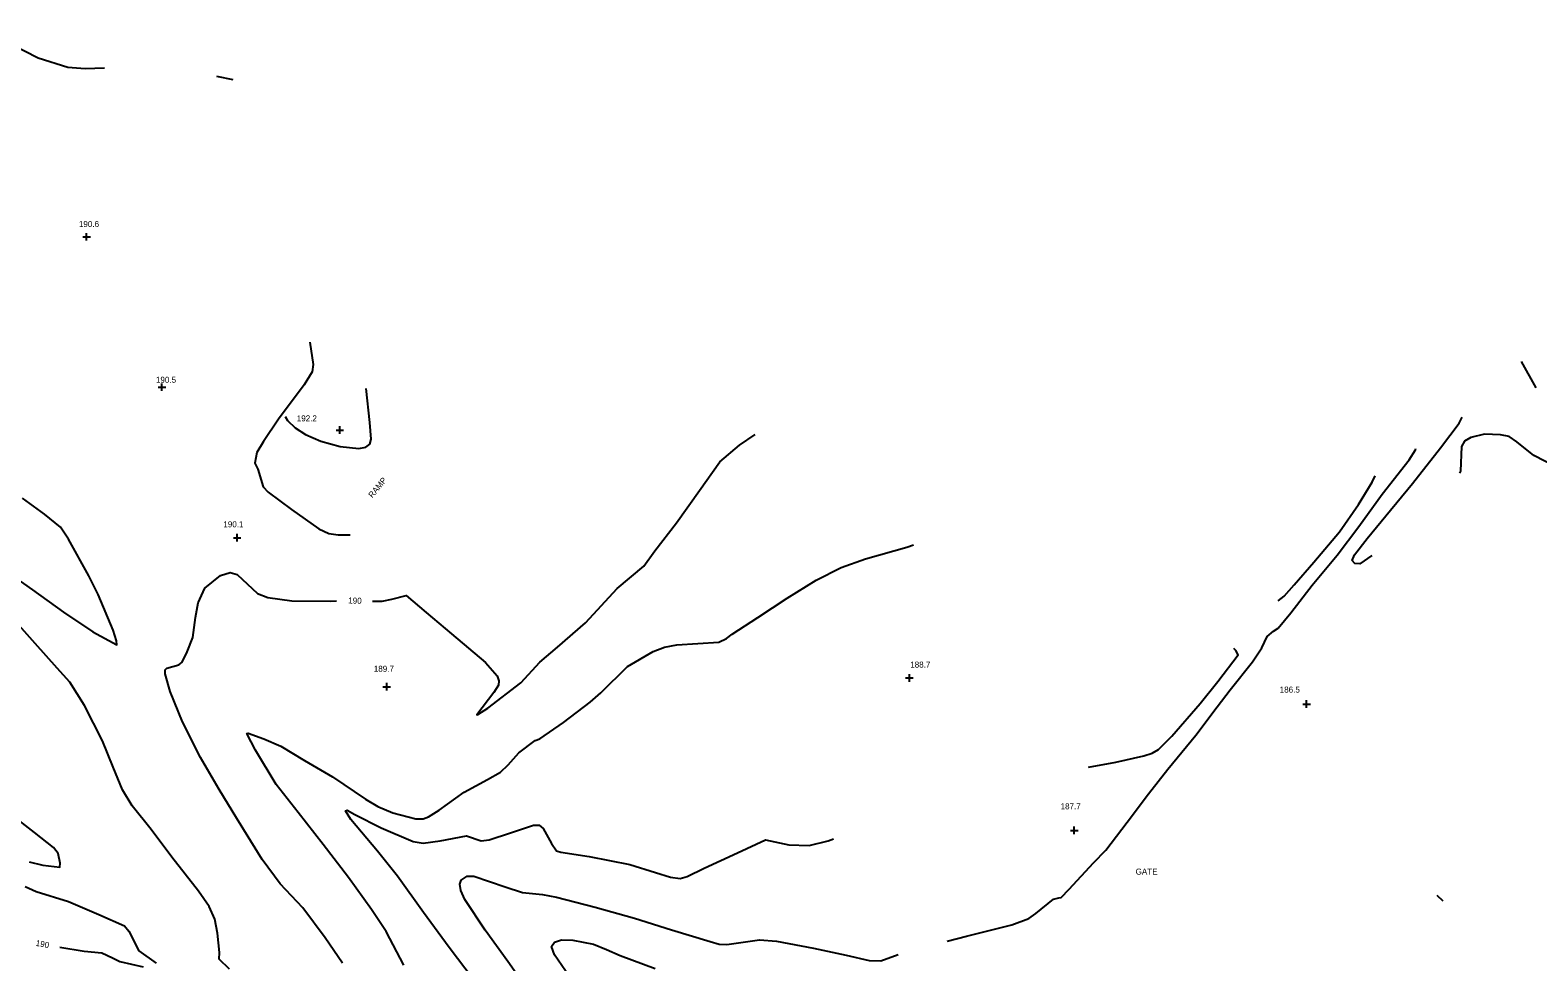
# Model space of a CAD drawing. Extents: x 1467615 to 2003689, y 770235 to 1108726.
# Drawn here: x 1995231 to 1995732, y 776984 to 777294 of the extents above; entities that cross this region are included whole.
import ezdxf

# ---------------------------------------------------------------- set-up
doc = ezdxf.new("R2010")
doc.units = 0
for name, color, linetype in [('RD_DTM_Major1', 7, 'Continuous'), ('RD_DTM_Major1_Lbl', 7, 'Continuous'), ('RD_DTM_Minor1', 7, 'Continuous'), ('RD_DTM_Spot_Elev', 7, 'Continuous'), ('RD_TX_Misc1', 7, 'Continuous')]:
    doc.layers.add(name, color=color, linetype=linetype)

msp = doc.modelspace()

# ---------------------------------------------------------------- linework, layer by layer
at = {"layer": 'RD_DTM_Major1'}
msp.add_line((1995731.45, 777174.81), (1995726.55, 777183.55), dxfattribs=at)
for points in [[(1995344.99, 777103.94), (1995348.16, 777103.86), (1995351.39, 777104.58), (1995356.09, 777105.75), (1995362.72, 777100.15), (1995371.16, 777093.09), (1995382.44, 777083.49), (1995386.33, 777079.12), (1995386.91, 777077.44), (1995386.75, 777076.02), (1995385.21, 777073.61), (1995379.55, 777066.14), (1995379.94, 777066.2), (1995383.22, 777068.33), (1995394.25, 777076.83), (1995400.51, 777083.66), (1995406.37, 777088.65), (1995415.73, 777096.7), (1995426.18, 777108.16), (1995435.08, 777115.59), (1995438.73, 777120.59), (1995445.91, 777129.91), (1995453.54, 777140.7), (1995460.3, 777150.18), (1995466.87, 777155.72), (1995472.09, 777159.26)], [(1995334.99, 776983.68), (1995329.2, 776992.08), (1995321.78, 777001.98), (1995314.32, 777010.01), (1995308.26, 777018.05), (1995299.89, 777031.68), (1995294.04, 777041.29), (1995287.86, 777051.96), (1995281.86, 777063.8), (1995277.71, 777073.89), (1995276.04, 777079.82), (1995276.11, 777081.1), (1995276.62, 777081.67), (1995280.62, 777082.71), (1995281.68, 777083.69), (1995283.43, 777087.1), (1995285.29, 777091.83), (1995286.17, 777098.47), (1995287.06, 777103.33), (1995289.27, 777108.19), (1995294.5, 777112.42), (1995297.64, 777113.39), (1995300.05, 777112.73), (1995306.74, 777106.48), (1995310.21, 777105.08), (1995318.14, 777103.99), (1995330.94, 777103.86), (1995332.99, 777104.03)], [(1995241.11, 776988.93), (1995249.15, 776987.6), (1995255.05, 776987.02), (1995258.63, 776985.43), (1995261.03, 776984.21), (1995268.76, 776982.39)]]:
    msp.add_lwpolyline(points, dxfattribs=at)
at = {"layer": 'RD_DTM_Minor1'}
for p, q in [((1995293.18, 777278.35), (1995298.61, 777277.3)), ((1995698.46, 777006.18), (1995700.45, 777004.39))]:
    msp.add_line(p, q, dxfattribs=at)
for points in [[(1995215.8, 777293.66), (1995233.93, 777284.46), (1995243.72, 777281.39), (1995249.47, 777280.95), (1995255.96, 777281.1)], [(1995324.13, 777189.93), (1995325.27, 777182.59), (1995324.93, 777180.17), (1995322.29, 777175.77), (1995313.68, 777164.34), (1995308.73, 777156.97), (1995306.51, 777153.34), (1995305.82, 777149.73), (1995306.84, 777147.75), (1995308.67, 777141.87), (1995310.32, 777140.08), (1995318, 777134.4), (1995327.09, 777128), (1995330.43, 777126.45), (1995333.56, 777125.96), (1995337.49, 777125.99)], [(1995315.99, 777165.26), (1995316.77, 777163.94), (1995319.3, 777161.53), (1995322.68, 777159.35), (1995327.74, 777157.07), (1995334.17, 777155.28), (1995340.46, 777154.69), (1995342.71, 777155.1), (1995344.02, 777156.12), (1995344.53, 777157.8), (1995344.11, 777163.25), (1995342.8, 777174.57)], [(1995676.83, 777119.08), (1995672.87, 777116.36), (1995671.24, 777116.47), (1995670.32, 777117.47), (1995671.09, 777119.34), (1995675.35, 777124.78), (1995681.53, 777132.3), (1995690.37, 777143.02), (1995699.65, 777154.88), (1995705.83, 777163.06), (1995706.93, 777165.03)], [(1995741.16, 777146.94), (1995730.73, 777152.37), (1995724.99, 777156.83), (1995722.49, 777158.61), (1995719.63, 777159.21), (1995714.28, 777159.45), (1995709.79, 777158.26), (1995707.61, 777157.03), (1995706.61, 777155.29), (1995706.35, 777147.14), (1995706, 777146.47)], [(1995535.79, 776990.96), (1995542.29, 776992.57), (1995557.26, 776996.33), (1995562.97, 776998.45), (1995565.29, 777000.16), (1995571.15, 777004.87), (1995572.86, 777005.37), (1995573.71, 777005.42), (1995576.37, 777008.24), (1995584.39, 777016.94), (1995588.53, 777021.15), (1995595.64, 777030.48), (1995602.71, 777039.88), (1995609.17, 777048.04), (1995618.38, 777059.44), (1995625.49, 777068.76), (1995629.83, 777074.48), (1995637.27, 777083.79), (1995640.32, 777088.44), (1995642.13, 777092.13), (1995644.26, 777093.95), (1995645.81, 777094.95), (1995650.01, 777100.05), (1995657.09, 777109.25), (1995665.39, 777119.21), (1995672.55, 777128.7), (1995680.31, 777139.44), (1995689.32, 777150.89), (1995691.42, 777154.23), (1995691.51, 777154.67)], [(1995645.81, 777104.07), (1995647.79, 777105.55), (1995651.09, 777109.29), (1995657.6, 777116.87), (1995666.1, 777126.93), (1995672.4, 777136.04), (1995677.01, 777143.5), (1995678.01, 777145.6)], [(1995221.01, 777115.3), (1995232.03, 777107.73), (1995242.35, 777100.28), (1995252.03, 777093.76), (1995260, 777089.45), (1995259.87, 777090.73), (1995258.82, 777094.26), (1995253.81, 777106.08), (1995250.76, 777112.38), (1995244.01, 777124.54), (1995241.33, 777128.45), (1995236.01, 777132.83), (1995228.69, 777138.13)], [(1995355.34, 776982.93), (1995349.47, 776994.18), (1995344.6, 777001.51), (1995336.98, 777012.07), (1995328.55, 777023.03), (1995320.31, 777033.68), (1995313, 777042.95), (1995306.06, 777054.38), (1995303.21, 777059.91), (1995303.61, 777060.05), (1995308.91, 777058.21), (1995314.46, 777055.75), (1995322.41, 777051.02), (1995331.68, 777045.59), (1995342.64, 777038.16), (1995346.69, 777035.74), (1995351.75, 777033.6), (1995359.3, 777031.59), (1995361.74, 777031.54), (1995363.56, 777032.2), (1995367.06, 777034.47), (1995375.43, 777040.43), (1995383.19, 777044.67), (1995387.44, 777047.04), (1995390.02, 777049.49), (1995393.57, 777053.49), (1995399, 777057.6), (1995400.5, 777058.19), (1995408.38, 777063.56), (1995417.25, 777070.31), (1995420.76, 777073.47), (1995429.6, 777082.2), (1995438.14, 777087.24), (1995441.91, 777088.63), (1995446.08, 777089.39), (1995460.03, 777090.3), (1995462.53, 777091.49), (1995464.43, 777092.92), (1995472.9, 777098.48), (1995482.68, 777104.92), (1995492.36, 777110.87), (1995500.67, 777115.1), (1995508.72, 777118.02), (1995522.46, 777121.89), (1995524.59, 777122.6)], [(1995297.44, 776981.58), (1995294.01, 776985.01), (1995294.12, 776987.19), (1995293.51, 776993.64), (1995292.58, 776998.2), (1995290.75, 777002.42), (1995287.17, 777007.54), (1995278.29, 777018.82), (1995271.42, 777027.99), (1995265.08, 777035.9), (1995261.96, 777041.22), (1995258.84, 777048.79), (1995255.3, 777057.51), (1995249.29, 777069.28), (1995244.47, 777077.01), (1995240.23, 777081.65), (1995232.86, 777089.87), (1995223.94, 777099.96)], [(1995582.81, 777048.76), (1995591.83, 777050.47), (1995601.15, 777052.48), (1995603.88, 777053.43), (1995605.99, 777054.68), (1995610.48, 777059.02), (1995619.83, 777069.91), (1995625.69, 777077.19), (1995632.47, 777086.09), (1995631.71, 777087.55), (1995631.05, 777088.17)], [(1995230.87, 777017.33), (1995235.48, 777016.2), (1995241.15, 777015.56), (1995241.26, 777016.88), (1995240.56, 777020.07), (1995238.99, 777022.01), (1995232.65, 777027.04), (1995221.73, 777035.6)], [(1995378.35, 776978.36), (1995370.36, 776988.85), (1995361.88, 777000.41), (1995353.25, 777012.54), (1995346.65, 777020.85), (1995337.79, 777031.36), (1995335.95, 777034.24), (1995336.48, 777034.42), (1995339.11, 777033.01), (1995347.83, 777028.63), (1995358.42, 777024.02), (1995361.82, 777023.5), (1995367.45, 777024.23), (1995376.21, 777025.98), (1995380.99, 777024.28), (1995383.67, 777024.59), (1995390.82, 777026.97), (1995398.39, 777029.5), (1995400.34, 777029.44), (1995401.59, 777028.42), (1995404.39, 777023.44), (1995406.03, 777020.91), (1995407.47, 777020.53), (1995416.95, 777019.03), (1995430.47, 777016.36), (1995438.94, 777013.78), (1995443.91, 777012.18), (1995447.09, 777011.8), (1995449.48, 777012.46), (1995455.15, 777015.2), (1995466.19, 777020.3), (1995475.48, 777024.57), (1995483.19, 777022.96), (1995489.96, 777022.72), (1995496.26, 777024.28), (1995498.07, 777024.95)], [(1995229.54, 777009.12), (1995233.24, 777007.48), (1995244.03, 777004.17), (1995254, 776999.75), (1995262.59, 776996.04), (1995264.04, 776994.3), (1995267.35, 776987.72), (1995273.04, 776983.67)], [(1995397.21, 776973.78), (1995389.94, 776984.22), (1995382.38, 776994.56), (1995375.63, 777004.83), (1995374.32, 777007.74), (1995373.99, 777009.86), (1995374.43, 777011.25), (1995376.34, 777012.5), (1995378.57, 777012.5), (1995388.98, 777008.95), (1995394.82, 777007.11), (1995401.36, 777006.46), (1995406.03, 777005.58), (1995418.94, 777002.22), (1995431.95, 776998.56), (1995444.21, 776994.75), (1995457.06, 776990.83), (1995460.13, 776989.93), (1995462.66, 776989.87), (1995473.51, 776991.42), (1995479.13, 776990.92), (1995491.38, 776988.56), (1995502.28, 776986.31), (1995509.87, 776984.54), (1995513.83, 776984.41), (1995519.57, 776986.54)], [(1995413.91, 776974), (1995405.43, 776986.35), (1995404.45, 776989.11), (1995405.35, 776990.59), (1995407.75, 776991.37), (1995411.45, 776991.3), (1995418.4, 776989.92), (1995422.63, 776988.17), (1995427.16, 776986.17), (1995438.79, 776981.81)]]:
    msp.add_lwpolyline(points, dxfattribs=at)
at = {"layer": 'RD_DTM_Spot_Elev'}
for p, q in [((1995248.75, 777225), (1995251.25, 777225)), ((1995250, 777223.75), (1995250, 777226.25)), ((1995273.75, 777175), (1995276.25, 777175)), ((1995275, 777173.75), (1995275, 777176.25)), ((1995332.84, 777160.78), (1995335.34, 777160.78)), ((1995334.09, 777159.53), (1995334.09, 777162.03)), ((1995298.75, 777125), (1995301.25, 777125)), ((1995300, 777123.75), (1995300, 777126.25)), ((1995523.26, 777077.15), (1995523.26, 777079.65)), ((1995348.43, 777075.49), (1995350.93, 777075.49)), ((1995349.68, 777074.24), (1995349.68, 777076.74)), ((1995522.01, 777078.4), (1995524.51, 777078.4)), ((1995653.96, 777069.72), (1995656.46, 777069.72)), ((1995655.21, 777068.47), (1995655.21, 777070.97)), ((1995578.05, 777026.51), (1995578.05, 777029.01)), ((1995576.8, 777027.76), (1995579.3, 777027.76))]:
    msp.add_line(p, q, dxfattribs=at)

# ---------------------------------------------------------------- texts
at = {"layer": 'RD_DTM_Major1_Lbl'}
for rotation, p in [(358.4759, (1995336.87, 777103.16)), (349.2842, (1995232.96, 776989.41))]:
    msp.add_text('190', height=2, rotation=rotation, dxfattribs=at).set_placement(p)
at = {"layer": 'RD_DTM_Spot_Elev'}
for s, p in [('190.6', (1995247.43, 777228.22)), ('190.5', (1995273.01, 777176.48)), ('192.2', (1995319.79, 777163.66)), ('190.1', (1995295.42, 777128.47)), ('189.7', (1995345.38, 777080.45)), ('188.7', (1995523.56, 777081.84)), ('186.5', (1995646.28, 777073.53)), ('187.7', (1995573.5, 777034.75))]:
    msp.add_text(s, height=2, dxfattribs=at).set_placement(p)
at = {"layer": 'RD_TX_Misc1'}
msp.add_text('RAMP', height=2, rotation=50.5089, dxfattribs=at).set_placement((1995344.92, 777138.06))
msp.add_text('GATE', height=2, dxfattribs=at).set_placement((1995598.42, 777013.05))

doc.saveas('drawing.dxf')
